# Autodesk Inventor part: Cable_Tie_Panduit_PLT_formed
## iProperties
Author: Mike Maenpaa
Shininess: 64.0
Angle Display Precision: 2
Document Length Units: 11272
Document Angle Units: 11286
Document Time Units: 11279
Document Mass Units: 11290
Document Length Units Precision: 3
Document Angle Units Precision: 2
Compacted: True
PropertySet Name: _Private Model Information
Created: 2002-09
Part Number: Cable_Tie_Panduit_PLT_formed
Material: Nylon-6/6 Natural
Document SubType Name: Modeling
Designer: Mike Maenpaa
Control State: 0
Master: False
Checked Out: False
PropertySet Name: Design Tracking Control
Density: 0.0
Volumn: 0.0
Area: 0.0
PropertySet Name: Model Information
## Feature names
1. Extrusion1
2. Extrusion2
3. Extrusion3
4. Fillet1
